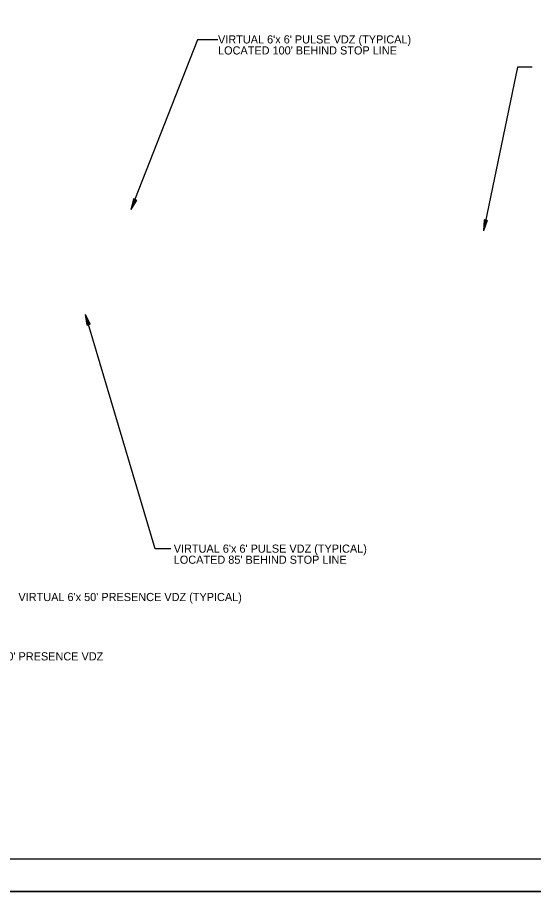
# Model space of a CAD drawing. Extents: x 660636 to 661659, y 641779 to 643841.
# Drawn here: x 661280.2 to 661470.1, y 642284 to 642605.7 of the extents above; entities that cross this region are included whole.
import ezdxf

# ---------------------------------------------------------------- set-up
doc = ezdxf.new("R2010")
doc.units = 0
for name, color, linetype in [('R_Border', 7, 'Continuous'), ('R_No Plot', 7, 'Continuous'), ('T_Drafting', 7, 'Continuous')]:
    doc.layers.add(name, color=color, linetype=linetype)

msp = doc.modelspace()

# ---------------------------------------------------------------- linework, layer by layer
at = {"layer": 'R_Border'}
msp.add_line((661644.3, 642295.93), (660695.76, 642295.93), dxfattribs=at)
at = {"layer": 'R_No Plot'}
msp.add_line((660658.55, 642284), (661658.55, 642284), dxfattribs=at)
msp.add_lwpolyline([(660658.53, 642924), (661658.55, 642924), (661658.55, 642283.98), (660658.53, 642283.98)], close=True, dxfattribs=at)
at = {"layer": 'T_Drafting'}
for p, q in [((661346.41, 642597.49), (661321.94, 642534.97)), ((661353.93, 642597.49), (661346.41, 642597.49)), ((661464.2, 642587.42), (661451.71, 642527.14)), ((661469.64, 642587.42), (661464.2, 642587.42)), ((661322.84, 642538.92), (661321.94, 642534.97)), ((661323.96, 642538.48), (661321.94, 642534.97)), ((661322.93, 642538.88), (661322.18, 642535.59)), ((661323.86, 642538.52), (661322.18, 642535.59)), ((661323.03, 642538.84), (661322.43, 642536.24)), ((661323.77, 642538.55), (661322.43, 642536.24)), ((661323.12, 642538.81), (661322.68, 642536.86)), ((661323.67, 642538.59), (661322.68, 642536.86)), ((661323.96, 642538.48), (661322.84, 642538.92)), ((661323.21, 642538.77), (661322.92, 642537.49)), ((661323.58, 642538.63), (661322.92, 642537.49)), ((661323.31, 642538.73), (661323.17, 642538.11)), ((661323.48, 642538.66), (661323.17, 642538.11)), ((661451.93, 642531.18), (661451.71, 642527.14)), ((661453.11, 642530.93), (661451.71, 642527.14)), ((661452.03, 642531.16), (661451.84, 642527.79)), ((661453.01, 642530.95), (661451.84, 642527.79)), ((661453.11, 642530.93), (661451.93, 642531.18)), ((661452.13, 642531.14), (661451.98, 642528.47)), ((661452.91, 642530.97), (661451.98, 642528.47)), ((661452.23, 642531.12), (661452.12, 642529.12)), ((661452.81, 642530.99), (661452.12, 642529.12)), ((661452.33, 642531.09), (661452.26, 642529.78)), ((661452.71, 642531.02), (661452.26, 642529.78)), ((661452.43, 642531.07), (661452.39, 642530.44)), ((661452.61, 642531.04), (661452.39, 642530.44)), ((661305.79, 642492.4), (661305.22, 642496.41)), ((661306.94, 642492.75), (661305.22, 642496.41)), ((661330.87, 642410.05), (661305.22, 642496.41)), ((661305.88, 642492.43), (661305.41, 642495.77)), ((661306.84, 642492.72), (661305.41, 642495.77)), ((661306.74, 642492.69), (661305.61, 642495.11)), ((661305.98, 642492.46), (661305.61, 642495.11)), ((661305.79, 642492.4), (661306.94, 642492.75)), ((661306.08, 642492.49), (661305.8, 642494.47)), ((661306.65, 642492.66), (661305.8, 642494.47)), ((661306.55, 642492.63), (661305.99, 642493.82)), ((661306.18, 642492.52), (661305.99, 642493.82)), ((661306.45, 642492.6), (661306.18, 642493.18)), ((661306.27, 642492.55), (661306.18, 642493.18)), ((661336.64, 642410.05), (661330.87, 642410.05))]:
    msp.add_line(p, q, dxfattribs=at)

# ---------------------------------------------------------------- texts
for s, p in [("VIRTUAL 6'x 6' PULSE VDZ (TYPICAL)", (661354.01, 642596.11)), ("LOCATED 100' BEHIND STOP LINE", (661354.01, 642592.05)), ("VIRTUAL 6'x 6' PULSE VDZ (TYPICAL)", (661337.72, 642408.68)), ("LOCATED 85' BEHIND STOP LINE", (661337.72, 642404.61)), ("VIRTUAL 6'x 50' PRESENCE VDZ (TYPICAL)", (661280.55, 642390.88)), ("VIRTUAL 6'x 30' PRESENCE VDZ", (661250.07, 642369.04))]:
    msp.add_text(s, height=3, dxfattribs=at).set_placement(p)

doc.saveas('drawing.dxf')
